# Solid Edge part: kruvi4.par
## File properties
Author: Mac
Template: Normal.par
Last saved by: Mac
Revision: 4
Application: Solid Edge
Material: Bronze, 90%
Face Style: Bronze
Fill Style: ANSI33(Brass)
Virtual Style: Brushed bronze
Coef. of Thermal Exp: 1.8e-05
Thermal Conductivity: 189.0
Specific Heat: 377.0
Modulus of Elasticity: 117210869000.0
Poission's Ratio: 0.36
Yield Stress: 372316878.0
Ultimate Stress: 420580177.0
Elongation: 0.0
Density: 8800,000 kg/m^3
Accuracy: 0,010
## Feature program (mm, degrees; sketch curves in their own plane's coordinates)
sketch for "unnamed Protrusion 1" plane through (0, 0, 0) normal (1, 0, 0) x-axis (0, 1, 0)
  circle centre (0.0026, 0) radius 0.3
extrude "unnamed Protrusion 1" add finite 2.3728 along -normal
lofted protrusion "unnamed LoftedProtrusion 1"
pattern "unnamed Pattern 1" of "unnamed LoftedProtrusion 1"
pattern "unnamed Pattern 2"
sketch for "unnamed Cutout 1" plane through (0.2791, 0.0026, 0) normal (1, 0, 0) x-axis (0, 1, 0)
  circle centre (0, 0) radius 0.366
extrude "unnamed Cutout 1" cut to key point along -normal
sketch for "ExtrudedCutout_2" plane through (-2.3728, 0.0026, 0) normal (-1, 0, 0) x-axis (0, -1, 0)
  circle centre (0, 0) radius 0.3547
extrude "ExtrudedCutout_2" cut finite 0.3354 along -normal
sketch for "unnamed Cutout 2" plane through (-2.0373, 0.0026, 0) normal (-1, 0, 0) x-axis (0, -1, 0)
  circle centre (0, 0) radius 0.2
extrude "unnamed Cutout 2" cut through along -normal
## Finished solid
Body 1: solid body, 24 faces, 63 edges, 40 vertices.
  Faces by surface: spline 16, plane 6, cylinder 2
  Edges by curve: circle 22, intersection 21, spline 16, curve on surface 4
Bounding box of the edges (mm; curved faces can reach further): 2.017 x 3.784 x 3.784, from (-2.0373, -1.8891, -1.8918) to (-0.0201, 1.8944, 1.8918).
Cylindrical faces by radius (mm): R0.2 x1, R0.3 x1
Planar faces by outward normal: +x 1, +y 1, +z 1, -x 1, -y 1, -z 1
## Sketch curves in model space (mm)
arc centre (-1.648, 0.4619, 1.8918) radius 0.0014 from (-1.6467, 0.4624, 1.8918) through (-1.6476, 0.4606, 1.8918) to (-1.6494, 0.4616, 1.8918)
spline (-1.7756, 0.5603, 1.8918) -> (-1.7025, 0.5285, 1.8918) -> (-1.6494, 0.4616, 1.8918)
arc centre (-1.7756, 0.5616, 1.8918) radius 0.0013 from (-1.7756, 0.5629, 1.8918) through (-1.7769, 0.5615, 1.8918) to (-1.7756, 0.5603, 1.8918)
spline (-1.7756, 0.5629, 1.8918) -> (-1.7053, 0.5364, 1.8918) -> (-1.6467, 0.4624, 1.8918)
arc centre (-1.3822, -0.0313, 1.7526) radius 0.0125 from (-1.3941, -0.035, 1.7526) through (-1.3793, -0.0434, 1.7526) to (-1.3697, -0.0307, 1.7526)
spline (-1.8863, 0.6103, 1.7526) -> (-1.6125, 0.3469, 1.7526) -> (-1.3941, -0.035, 1.7526)
arc centre (-1.88, 0.6236, 1.7526) radius 0.0147 from (-1.87, 0.6343, 1.7526) through (-1.8926, 0.6311, 1.7526) to (-1.8863, 0.6103, 1.7526)
spline (-1.87, 0.6343, 1.7526) -> (-1.546, 0.34, 1.7526) -> (-1.3697, -0.0307, 1.7526)
arc centre (-0.7573, -0.5714, 1.2) radius 0.0237 from (-0.7356, -0.5618, 1.2) through (-0.7481, -0.5933, 1.2) to (-0.7782, -0.5827, 1.2)
spline (-2, 0.5574, 1.2) -> (-1.3412, 0.222, 1.2) -> (-0.7782, -0.5827, 1.2)
arc centre (-1.9952, 0.5785, 1.2) radius 0.0216 from (-1.9904, 0.5995, 1.2) through (-2.0164, 0.5826, 1.2) to (-2, 0.5574, 1.2)
spline (-1.9904, 0.5995, 1.2) -> (-1.2534, 0.2789, 1.2) -> (-0.7356, -0.5618, 1.2)
arc centre (-0.0072, -0.2062, 0) radius 0.0386 from (0, -0.244, 0) through (0.0314, -0.205, 0) to (0, -0.1683, 0)
spline (-2, 0.2493, 0) -> (-1.0025, 0.1403, 0) -> (0, -0.1683, 0)
arc centre (-1.9792, 0.2041, 0) radius 0.0498 from (-2, 0.2493, 0) through (-2.029, 0.2041, 0) to (-2, 0.1588, 0)
spline (-2, 0.1588, 0) -> (-1.1093, -0.1294, 0) -> (0, -0.244, 0)
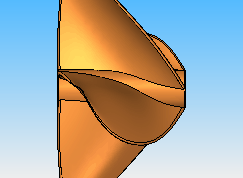
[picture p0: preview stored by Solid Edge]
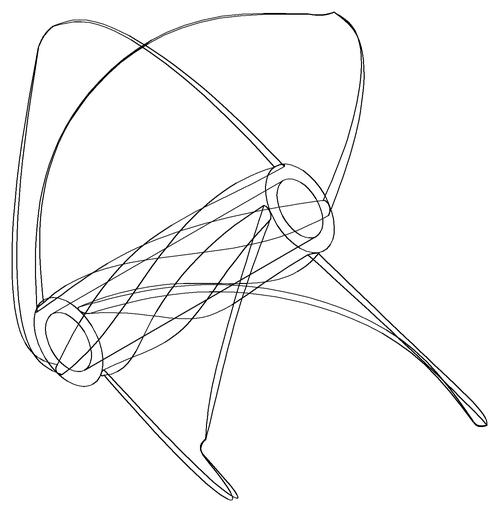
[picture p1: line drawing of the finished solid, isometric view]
